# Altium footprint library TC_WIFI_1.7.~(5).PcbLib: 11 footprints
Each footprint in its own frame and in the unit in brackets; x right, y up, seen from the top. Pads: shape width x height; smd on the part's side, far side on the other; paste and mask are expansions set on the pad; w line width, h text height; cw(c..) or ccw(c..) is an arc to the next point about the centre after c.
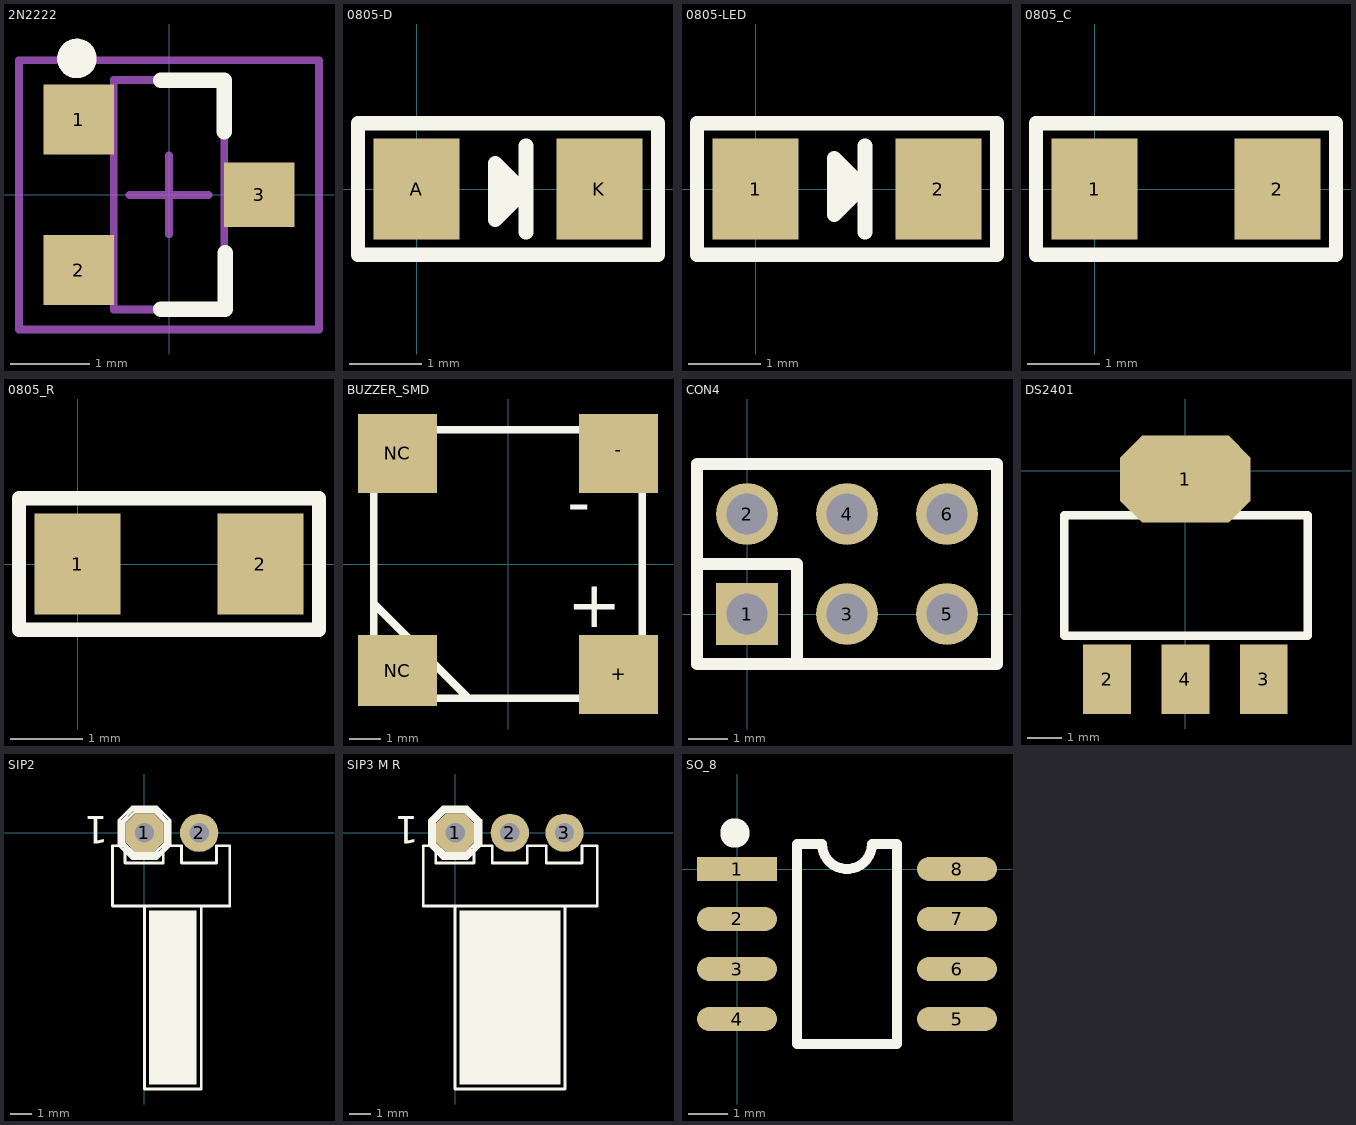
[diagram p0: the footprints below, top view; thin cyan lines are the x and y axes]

## 2N2222 [mil]
pads (3):
  rect 35x35 smd: 1(-45,37.5) 2(-45,-37.5)
  rect 35x32 smd: 3(45,0)
Top Overlay:
  circle w9.84: c-45.92,68 r4.92
  lines w7.87: -3.94,-57.09 28,-57.09 28,-29 ; -3.94,57.09 27.56,57.09 27.56,31.5
Mechanical 13:
  lines w3.94: -27.56,-57.28 -27.56,57.28 27.56,57.28 27.56,-57.28 -27.56,-57.28
Mechanical 15:
  lines w3.94: -19.69,0 19.68,0 ; 0,-19.68 0,19.69 ; -74.8,-67.13 -74.8,67.13 74.8,67.13 74.8,-67.13 -74.8,-67.13
3D body "SW3dPS-sot-3p290x130ll237h100.STEP": height 39.57, standoff 0, extent -48.65,-56 44.65,58.17

## 0805-D [mm]
pads (2):
  rect 1.2x1.4 smd: A(0,0) K(2.54,0)
Top Overlay:
  lines w0.2: -0.813,-0.914 -0.813,-0.864 -0.813,0.914 -0.762,0.914 3.353,0.914 3.353,-0.914 -0.813,-0.914
  lines w0.203: 1.475,-0.045 1.094,-0.426 1.094,0.356 1.475,-0.025 ; 1.52,-0.6 1.52,0.6
  lines w0.305: 1.15,-0.025 1.432,-0.025
3D body "User Library-SOD523-2.step": height 0.65, standoff 0, extent 0.42,-0.425 2.07,0.374

## 0805-LED [mm]
pads (2):
  rect 1.2x1.4 smd: 1(0,0) 2(2.54,0)
Top Overlay:
  lines w0.2: -0.813,-0.914 3.327,-0.914 3.353,-0.914 3.353,0.914 -0.787,0.914 -0.813,0.914 -0.813,-0.889 -0.813,-0.914
  lines w0.203: 1.475,0.025 1.094,-0.356 1.094,0.426 1.475,0.045 ; 1.52,-0.6 1.52,0.6
  lines w0.305: 1.15,0.025 1.432,0.025
3D body "User Library-User Library-led_0805 GRE.step": height 1.1, standoff 0, extent 0.254,-0.619 2.274,0.631

## 0805_C [mm]
pads (2):
  rect 1.2x1.4 smd: 1(0,0) 2(2.54,0)
Top Overlay:
  lines w0.2: -0.813,-0.914 3.353,-0.914 3.353,0.914 -0.813,0.914 -0.813,-0.914
3D body "74634.stp": height 0.86, standoff -0.02, extent 0.145,-0.737 2.345,0.713

## 0805_R [mm]
pads (2):
  rect 1.2x1.4 smd: 1(0,0) 2(2.54,0)
Top Overlay:
  lines w0.2: -0.813,-0.914 3.353,-0.914 3.353,0.914 -0.762,0.914 -0.813,0.914 -0.813,-0.914
3D body "User Library-0805 SMD Resistor.step": height 0.78, standoff 0, extent 0.296,-0.625 2.296,0.625

## BUZZER_SMD [mil]
pads (4):
  rect 100x100 smd: +(140,-140) -(140,140) NC(-140,140)
  rect 100x90 smd: NC(-140,-135)
Top Overlay:
  lines w10: -170,-90 -170,90 ; -170,-50 -50,-170 ; -90,-170 90,-170 ; -90,170 90,170 ; 170,-90 170,90
  text "-" at 75,50 h60
  text "+" at 75,-80 h60
3D body "CMT-8540S-SMT.stp": height 159.37, standoff 1.89, extent -170,-167.32 164.65,167.32

## CON4 [mil]
pads (6):
  rect 62x62 hole 41: 1(0,0)
  round 62 hole 41: 2(0,100) 3(100,0) 4(100,100) 5(200,0) 6(200,100)
Top Overlay:
  lines w12: -50,-50 -50,150 250,150 250,-50 -50,-50 ; -50,-50 -50,50 50,50 50,-50 -50,-50
3D body "User Library-IDC6.STEP": height 313.07, standoff -120, extent -50,-49.99 250,150.01

## DS2401 [mil]
pads (4):
  oct 150x100 smd: 1(0,-10)
  rect 55x80 smd: 2(-90,-240) 3(90,-240) 4(0,-240)
Top Overlay:
  lines w10: -139.33,-190 -139.33,-51.54 140.67,-51.54 140.67,-190 -139.33,-190
3D body "CircuitWorks-SOT-223.step": height 65.43, standoff -0.71, extent -127.84,-262.56 128.07,11.46

## SIP2 [mil]
pads (2):
  oct 70x70 hole 35.43: 1(0,0)
  round 70 hole 35.43: 2(100,0)
Top Overlay:
  region: 95,-141.73 7.87,-141.73 7.87,-460.62 95,-460.62
  lines w5: -18.68,37.59 18.7,37.59 ; -18.51,37.59 -37.4,18.7 -37.4,-18.7 -18.7,-37.4 18.7,-37.4 37.43,-18.68 37.43,18.7 18.54,37.59 ; 0,-133.86 0,-468.5 104,-468.5 104,-133.86 ; 46.26,-23.62 22.64,-47.24 -22.64,-47.24 -47.24,-22.64 -47.24,22.64 -22.64,47.24 22.64,47.24 47.24,22.64 47.24,-23.62 ; -58.27,-133.86 156,-133.86 156,-23.62 131.89,-23.62 131.89,-55.12 67.91,-55.12 67.91,-23.62 34.45,-23.62 34.45,-55.12 -35.43,-55.12 -35.43,-23.62 -58.27,-23.62 -58.27,-133.86 ; -42.32,-20.67 -42.32,20.67 -20.67,42.32 20.67,42.32 42.32,20.67 42.32,-20.67 34.45,-28.54 20.67,-42.32 -20.67,-42.32 -42.32,-20.67
  text "1" at -66.31,30 h50

## SIP3 M R [mil]
pads (3):
  oct 70x70 hole 35.43: 1(0,0)
  round 70 hole 35.43: 2(100,0) 3(200,0)
Top Overlay:
  region: 192.91,-141.73 7.87,-141.73 7.87,-460.62 192.91,-460.62
  lines w5: -18.68,37.59 18.7,37.59 ; -18.51,37.59 -37.4,18.7 -37.4,-18.7 -18.7,-37.4 18.7,-37.4 37.43,-18.68 37.43,18.7 18.54,37.59 ; 0,-133.86 0,-468.5 200.79,-468.5 200.79,-133.86 ; 46.26,-23.62 22.64,-47.24 -22.64,-47.24 -47.24,-22.64 -47.24,22.64 -22.64,47.24 22.64,47.24 47.24,22.64 47.24,-23.62 ; -58.27,-133.86 -58.27,-23.62 -35.43,-23.62 -35.43,-55.12 34.45,-55.12 34.45,-23.62 67.91,-23.62 67.91,-55.12 131.89,-55.12 131.89,-23.62 166.93,-23.62 166.93,-55.12 231.89,-55.12 231.89,-23.62 259.84,-23.62 259.84,-133.86 -58.27,-133.86 ; -42.32,-20.67 -42.32,20.67 -20.67,42.32 20.67,42.32 42.32,20.67 42.32,-20.67 34.45,-28.54 20.67,-42.32 -20.67,-42.32 -42.32,-20.67
  text "1" at -66.31,30 h50

## SO_8 [mil]
pads (8):
  rect 80x24 smd: 1(0,0)
  oval 80x24 smd: 2(0,-50) 3(0,-100) 4(0,-150) 5(220,-150) 6(220,-100) 7(220,-50) 8(220,0)
Top Overlay:
  circle w25: c-2,36 r2.24
  lines w10: 60,-175 160,-175 160,25 135,25 cw(c110,25) 85,25 60,25 60,-175
3D body "CircuitWorks-SO-8 (PIC12FXXX).step": height 62.99, standoff 0, extent -7.91,-171.45 227.91,21.46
